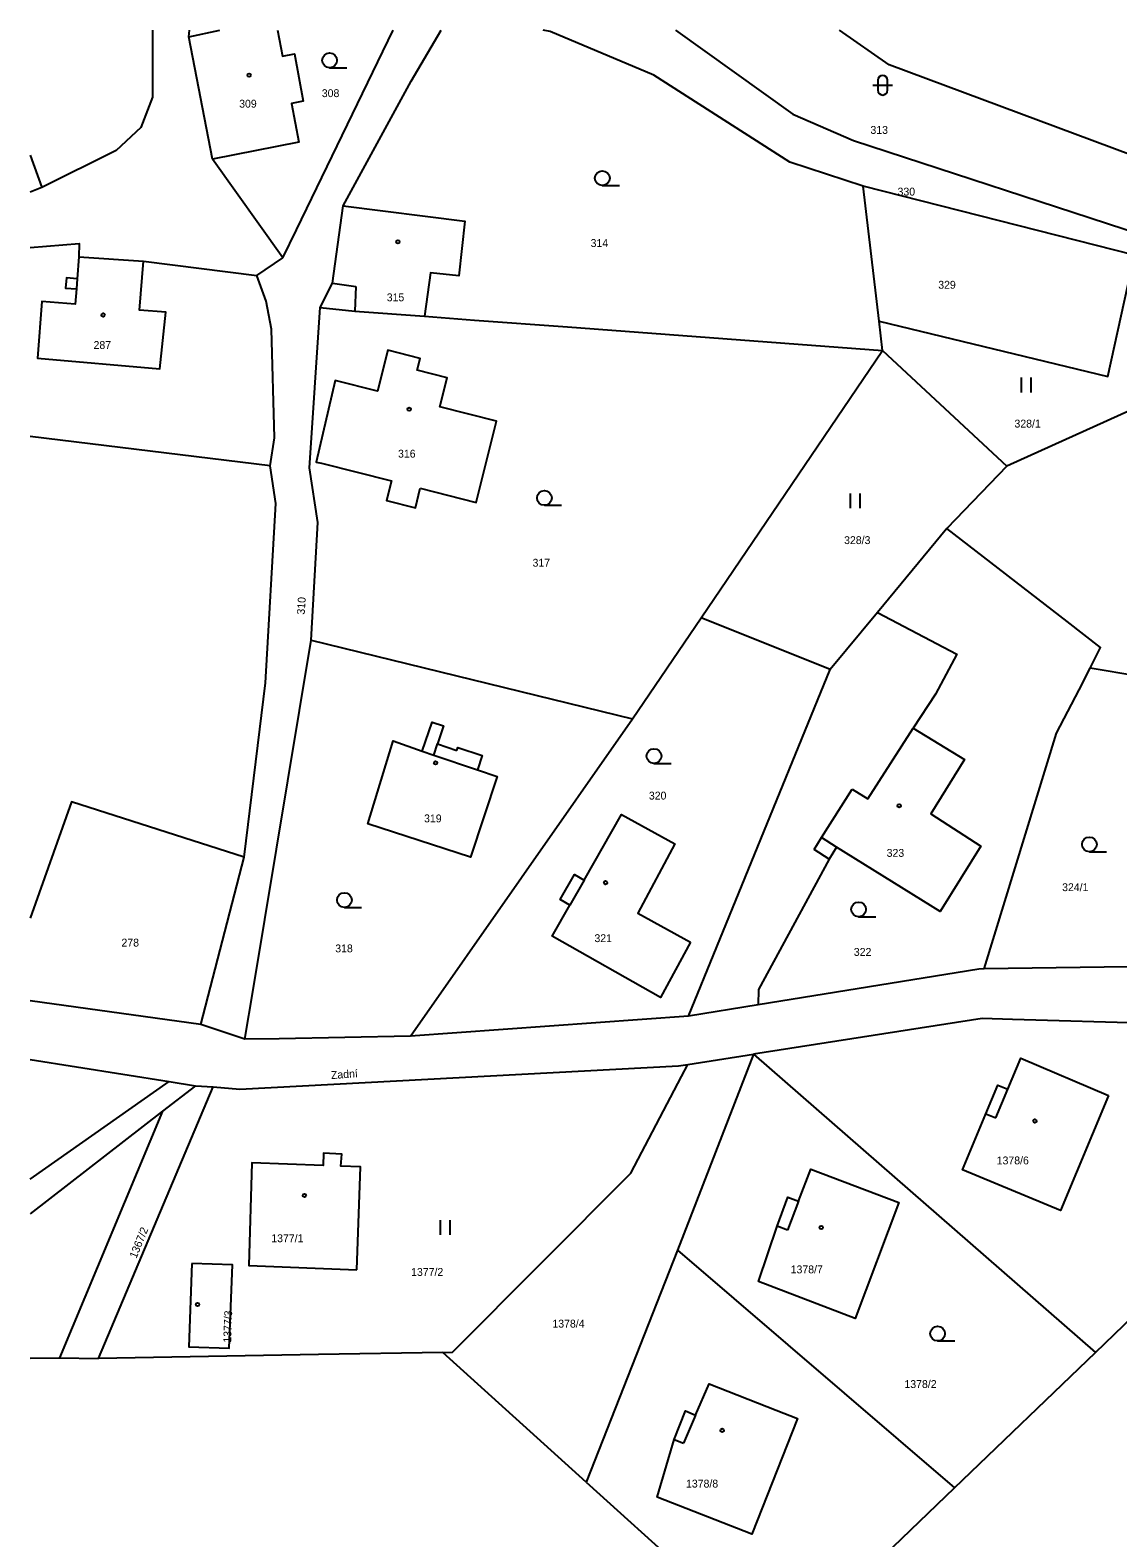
# Model space of a CAD drawing. Extents: x -719706 to -718922, y -950351 to -949651.
# Drawn here: x -719705.6 to -719594.9, y -949804.5 to -949651 of the extents above; entities that cross this region are included whole.
import ezdxf

# ---------------------------------------------------------------- set-up
doc = ezdxf.new("R2010")
doc.units = 0
doc.layers.add('Doplňující texty', color=7, linetype='Continuous')

msp = doc.modelspace()

# ---------------------------------------------------------------- linework, layer by layer
at = {"layer": 'Doplňující texty'}
for p, q in [((-719687.02, -949664.16), (-719689.45, -949651.7)), ((-719675.12, -949654.86), (-719673.37, -949654.86)), ((-719619.82, -949656.64), (-719617.82, -949656.64)), ((-719619.32, -949656.14), (-719619.32, -949657.14)), ((-719618.32, -949657.14), (-719618.32, -949656.14)), ((-719679.88, -949674.21), (-719687.02, -949664.16)), ((-719704.4, -949667.05), (-719705.59, -949667.51)), ((-719647.36, -949666.85), (-719645.61, -949666.85)), ((-719619.19, -949680.65), (-719620.8, -949666.93)), ((-719593.21, -949673.95), (-719620.8, -949666.93)), ((-719700.63, -949674.09), (-719694.07, -949674.55)), ((-719682.52, -949675.99), (-719679.88, -949674.21)), ((-719694.07, -949674.55), (-719682.52, -949675.99)), ((-719700.8, -949676.33), (-719700.89, -949677.37)), ((-719674.83, -949676.8), (-719672.45, -949677.12)), ((-719672.45, -949677.12), (-719672.54, -949679.63)), ((-719618.84, -949683.63), (-719619.19, -949680.65)), ((-719637.3, -949710.86), (-719618.84, -949683.63)), ((-719618.84, -949683.63), (-719606.19, -949695.42)), ((-719582.02, -949684.5), (-719606.19, -949695.42)), ((-719604.71, -949687.9), (-719604.71, -949686.4)), ((-719603.71, -949687.9), (-719603.71, -949686.4)), ((-719681.15, -949695.38), (-719705.59, -949692.38)), ((-719606.19, -949695.42), (-719612.3, -949701.77)), ((-719622.11, -949699.68), (-719622.11, -949698.18)), ((-719621.11, -949699.68), (-719621.11, -949698.18)), ((-719653.25, -949699.39), (-719651.5, -949699.39)), ((-719612.3, -949701.77), (-719619.36, -949710.29)), ((-719644.29, -949721.13), (-719637.3, -949710.86)), ((-719624.18, -949716.11), (-719637.3, -949710.86)), ((-719619.36, -949710.29), (-719624.18, -949716.11)), ((-719677, -949713.12), (-719644.29, -949721.13)), ((-719638.59, -949751.38), (-719624.18, -949716.11)), ((-719666.88, -949753.42), (-719644.29, -949721.13)), ((-719620.35, -949729.26), (-719615.72, -949722.07)), ((-719665.69, -949724.41), (-719664.51, -949724.81)), ((-719664.51, -949724.81), (-719664.13, -949723.67)), ((-719664.51, -949724.81), (-719660.07, -949726.31)), ((-719642.1, -949725.67), (-719640.35, -949725.67)), ((-719625.05, -949733.21), (-719621.94, -949728.28)), ((-719621.94, -949728.28), (-719620.35, -949729.26)), ((-719625.81, -949734.44), (-719625.05, -949733.21)), ((-719623.51, -949734.17), (-719625.05, -949733.21)), ((-719688.21, -949752.22), (-719683.81, -949735.2)), ((-719624.28, -949735.4), (-719625.81, -949734.44)), ((-719597.78, -949734.66), (-719596.03, -949734.66)), ((-719649.21, -949737.54), (-719650.65, -949740.08)), ((-719673.61, -949740.32), (-719671.86, -949740.32)), ((-719621.28, -949741.27), (-719619.53, -949741.27)), ((-719580.8, -949746.19), (-719608.49, -949746.58)), ((-719688.21, -949752.22), (-719705.59, -949749.83)), ((-719631.5, -949750.23), (-719638.59, -949751.38)), ((-719683.73, -949753.74), (-719688.21, -949752.22)), ((-719638.59, -949751.38), (-719666.88, -949753.42)), ((-719589.32, -949752.18), (-719605.6, -949751.73)), ((-719631.96, -949755.26), (-719639.72, -949775.19)), ((-719638.64, -949756.3), (-719631.96, -949755.26)), ((-719631.96, -949755.26), (-719597.18, -949785.61)), ((-719639.29, -949757.54), (-719638.64, -949756.3)), ((-719705.59, -949767.97), (-719691.45, -949758.03)), ((-719698.63, -949786.24), (-719686.97, -949758.59)), ((-719688.75, -949758.46), (-719692.11, -949761.06)), ((-719691.45, -949758.03), (-719688.75, -949758.46)), ((-719688.75, -949758.46), (-719686.97, -949758.59)), ((-719607.32, -949761.74), (-719606.1, -949758.83)), ((-719692.11, -949761.06), (-719705.59, -949771.49)), ((-719692.11, -949761.06), (-719702.6, -949786.15)), ((-719608.32, -949761.32), (-719607.32, -949761.74)), ((-719627.4, -949770.21), (-719628.51, -949773.15)), ((-719663.84, -949773.65), (-719663.84, -949772.15)), ((-719662.84, -949773.65), (-719662.84, -949772.15)), ((-719597.18, -949785.61), (-719582.76, -949771.75)), ((-719628.51, -949773.15), (-719629.58, -949772.75)), ((-719639.72, -949775.19), (-719648.99, -949798.8)), ((-719639.72, -949775.19), (-719611.51, -949799.38)), ((-719613.24, -949784.44), (-719611.49, -949784.44)), ((-719702.6, -949786.15), (-719698.63, -949786.24)), ((-719648.99, -949798.8), (-719663.6, -949785.6)), ((-719611.51, -949799.38), (-719597.18, -949785.61)), ((-719637.86, -949791.98), (-719639.1, -949794.86)), ((-719640.03, -949794.48), (-719639.1, -949794.86)), ((-719648.99, -949798.8), (-719629.37, -949816.54)), ((-719629.37, -949816.54), (-719611.51, -949799.38))]:
    msp.add_line(p, q, dxfattribs=at)
for points in [[(-719693.13, -949651.04), (-719693.13, -949657.85), (-719694.34, -949660.95), (-719696.84, -949663.29), (-719704.4, -949667.05)], [(-719689.45, -949651.7), (-719689.37, -949651.04)], [(-719689.45, -949651.7), (-719686.3, -949651.04)], [(-719680.41, -949651.04), (-719679.91, -949653.68), (-719678.7, -949653.45), (-719677.8, -949658.27), (-719679, -949658.49), (-719678.26, -949662.45), (-719687.02, -949664.16)], [(-719679.88, -949674.21), (-719678.5, -949671.37), (-719668.64, -949651.04)], [(-719673.75, -949668.9), (-719666.8, -949656.22), (-719663.76, -949651.04)], [(-719620.8, -949666.93), (-719628.27, -949664.48), (-719642.12, -949655.62), (-719652.67, -949651.17), (-719653.37, -949651.04)], [(-719639.91, -949651.04), (-719627.98, -949659.57), (-719621.79, -949662.27), (-719592.52, -949671.82)], [(-719593.5, -949663.75), (-719618.16, -949654.55), (-719623.21, -949651.04)], [(-719705.59, -949663.75), (-719704.4, -949667.05)], [(-719676.07, -949679.27), (-719674.83, -949676.8), (-719673.75, -949668.9)], [(-719673.75, -949668.9), (-719661.34, -949670.48), (-719661.96, -949676.05), (-719664.83, -949675.73), (-719665.46, -949680.16)], [(-719705.59, -949673.15), (-719700.62, -949672.75), (-719700.63, -949674.09)], [(-719700.63, -949674.09), (-719700.8, -949676.33), (-719701.9, -949676.24), (-719701.99, -949677.29), (-719700.89, -949677.37), (-719701.01, -949678.91), (-719704.39, -949678.64), (-719704.84, -949684.41), (-719692.4, -949685.5), (-719691.78, -949679.74), (-719694.48, -949679.53), (-719694.07, -949674.55)], [(-719619.19, -949680.65), (-719595.9, -949686.29), (-719593.21, -949673.95)], [(-719681.15, -949695.38), (-719680.74, -949692.52), (-719681.02, -949681.47), (-719681.56, -949678.62), (-719682.52, -949675.99)], [(-719677, -949713.12), (-719676.31, -949701.16), (-719677.16, -949695.58), (-719676.07, -949679.27)], [(-719676.07, -949679.27), (-719672.54, -949679.63), (-719665.46, -949680.16)], [(-719665.46, -949680.16), (-719660.37, -949680.54), (-719650.9, -949681.24), (-719618.84, -949683.63)], [(-719665.89, -949697.66), (-719660.2, -949699.1), (-719658.13, -949690.83), (-719663.89, -949689.37), (-719663.15, -949686.41), (-719666.21, -949685.63), (-719665.91, -949684.44), (-719669.18, -949683.61), (-719670.23, -949687.77), (-719674.55, -949686.68), (-719676.48, -949694.99), (-719675.95, -949695.12), (-719668.83, -949696.92), (-719669.33, -949698.91), (-719666.39, -949699.65), (-719665.89, -949697.66)], [(-719683.81, -949735.2), (-719681.65, -949717.45), (-719680.6, -949699.2), (-719681.15, -949695.38)], [(-719597.72, -949715.98), (-719596.66, -949713.87), (-719600.04, -949711.23), (-719612.3, -949701.77)], [(-719619.36, -949710.29), (-719611.29, -949714.53), (-719613.46, -949718.6), (-719615.72, -949722.07), (-719610.51, -949725.25), (-719613.92, -949730.78), (-719608.85, -949734.09), (-719612.96, -949740.73), (-719623.51, -949734.17), (-719624.28, -949735.4), (-719631.48, -949748.66), (-719631.5, -949750.23)], [(-719683.73, -949753.74), (-719682.89, -949748.72), (-719677, -949713.12)], [(-719608.49, -949746.58), (-719601.14, -949722.59), (-719598.82, -949718.17), (-719597.72, -949715.98)], [(-719570, -949720.95), (-719573.78, -949720.58), (-719592.85, -949716.78), (-719597.72, -949715.98)], [(-719662.16, -949724.34), (-719662.05, -949724.03), (-719659.58, -949724.86), (-719660.07, -949726.31), (-719658.05, -949727), (-719660.77, -949735.22), (-719671.21, -949731.8), (-719668.63, -949723.35), (-719665.69, -949724.41), (-719664.69, -949721.45), (-719663.51, -949721.85), (-719664.13, -949723.67), (-719662.16, -949724.34)], [(-719683.81, -949735.2), (-719701.39, -949729.57), (-719705.59, -949741.42)], [(-719638.4, -949743.86), (-719641.43, -949749.5), (-719652.45, -949743.25), (-719650.65, -949740.08), (-719651.64, -949739.52), (-719650.2, -949736.98), (-719649.21, -949737.54), (-719645.42, -949730.85), (-719639.99, -949733.86), (-719643.73, -949740.91), (-719638.4, -949743.86)], [(-719608.49, -949746.58), (-719609.04, -949746.59), (-719631.5, -949750.23)], [(-719605.6, -949751.73), (-719608.7, -949751.64), (-719631.96, -949755.26)], [(-719666.88, -949753.42), (-719680.25, -949753.68), (-719683.73, -949753.74)], [(-719705.59, -949755.8), (-719691.45, -949758.03)], [(-719595.85, -949759.46), (-719600.74, -949771.17), (-719610.69, -949767.01), (-719608.32, -949761.32), (-719607.1, -949758.41), (-719606.1, -949758.83), (-719604.78, -949755.67), (-719595.85, -949759.46)], [(-719686.97, -949758.59), (-719684.24, -949758.8), (-719639.62, -949756.45), (-719638.64, -949756.3)], [(-719663.6, -949785.6), (-719662.61, -949785.58), (-719644.46, -949767.37), (-719639.29, -949757.54)], [(-719672.36, -949777.19), (-719671.98, -949766.71), (-719673.97, -949766.64), (-719673.88, -949765.43), (-719675.73, -949765.34), (-719675.77, -949766.57), (-719683.04, -949766.3), (-719683.34, -949776.77), (-719672.36, -949777.19)], [(-719629.58, -949772.75), (-719628.47, -949769.8), (-719627.4, -949770.21), (-719626.12, -949766.97), (-719617.17, -949770.36), (-719621.63, -949782.14), (-719631.46, -949778.4), (-719629.58, -949772.75)], [(-719689.14, -949776.55), (-719689.46, -949785.03), (-719685.33, -949785.18), (-719685.01, -949776.71), (-719689.14, -949776.55)], [(-719705.59, -949786.21), (-719702.6, -949786.15)], [(-719663.6, -949785.6), (-719676.23, -949785.83), (-719698.63, -949786.24)], [(-719637.86, -949791.98), (-719636.49, -949788.8), (-719629.66, -949791.5), (-719627.51, -949792.35), (-719632.15, -949804.09), (-719641.77, -949800.34), (-719640.03, -949794.48), (-719638.88, -949791.57), (-719637.86, -949791.98)]]:
    msp.add_lwpolyline(points, dxfattribs=at)
for centre, radius in [((-719675.12, -949654.11), 0.75), ((-719683.31, -949655.62), 0.175), ((-719647.36, -949666.1), 0.75), ((-719668.16, -949672.58), 0.175), ((-719698.17, -949680.03), 0.175), ((-719667.02, -949689.62), 0.175), ((-719653.25, -949698.64), 0.75), ((-719642.1, -949724.92), 0.75), ((-719664.33, -949725.61), 0.175), ((-719617.15, -949729.97), 0.175), ((-719597.78, -949733.91), 0.75), ((-719673.61, -949739.57), 0.75), ((-719647.03, -949737.8), 0.175), ((-719621.28, -949740.52), 0.75), ((-719603.33, -949762.06), 0.175), ((-719677.68, -949769.63), 0.175), ((-719625.08, -949772.89), 0.175), ((-719688.55, -949780.73), 0.175), ((-719613.24, -949783.69), 0.75), ((-719635.16, -949793.54), 0.175)]:
    msp.add_circle(centre, radius, dxfattribs=at)
for centre, start, end in [((-719618.82, -949656.14), 0, 180), ((-719618.82, -949657.14), 180, 359.9879)]:
    msp.add_arc(centre, 0.5, start, end, dxfattribs=at)

# ---------------------------------------------------------------- texts
for s, p in [('308', (-719675.91, -949657.85)), ('309', (-719684.32, -949658.92)), ('313', (-719620.07, -949661.59)), ('330', (-719617.31, -949667.87)), ('314', (-719648.55, -949673.1)), ('329', (-719613.17, -949677.35)), ('315', (-719669.3, -949678.63)), ('287', (-719699.14, -949683.48)), ('328/1', (-719605.41, -949691.48)), ('316', (-719668.15, -949694.54)), ('328/3', (-719622.75, -949703.34)), ('317', (-719654.46, -949705.64)), ('320', (-719642.62, -949729.34)), ('319', (-719665.5, -949731.66)), ('323', (-719618.42, -949735.17)), ('324/1', (-719600.56, -949738.66)), ('278', (-719696.3, -949744.3)), ('321', (-719648.16, -949743.85)), ('318', (-719674.54, -949744.89)), ('322', (-719621.76, -949745.25)), ('1378/6', (-719607.22, -949766.47)), ('1377/1', (-719681.05, -949774.39)), ('1377/2', (-719666.82, -949777.82)), ('1378/7', (-719628.19, -949777.56)), ('1378/4', (-719652.44, -949783.08)), ('1378/2', (-719616.61, -949789.23)), ('1378/8', (-719638.84, -949799.36))]:
    msp.add_text(s, height=0.8, dxfattribs=at).set_placement(p)
for s, rotation, p in [('310', 86, (-719677.66, -949710.54)), ('Zadní', 4, (-719674.95, -949757.79)), ('1367/2', 68, (-719694.78, -949776.1)), ('1377/3', 88, (-719685.14, -949784.63))]:
    msp.add_text(s, height=0.8, rotation=rotation, dxfattribs=at).set_placement(p)

doc.saveas('drawing.dxf')
